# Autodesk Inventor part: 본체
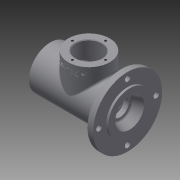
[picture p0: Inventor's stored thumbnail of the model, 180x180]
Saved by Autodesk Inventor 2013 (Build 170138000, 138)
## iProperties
Created: 2016-08
Part Number: 본체
Material: 일반
Document SubType Name: Modeling
Designer: Administrator
Density: 1 g/cm^3
Author: Administrator
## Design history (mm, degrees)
sketch "스케치1"
  geometry: C1 r 31 at (0, 0); C2 r 26 at (0, 0); 1 further point
  constraints: 2 centre point, 2 coincident
  dimensions: "d8" = 62 diameter of C1; "d9" = 52 diameter of C2
extrude "돌출1" new body sketch "스케치1" stored distance "d10" = 115; taper "d11" = 0 deg
sketch "스케치2"
  geometry: L1 (-57.5, -31)-(-57.5, 31) reference; L2 (-57.5, 31)-(57.5, 31) reference; L3 (57.5, 31)-(57.5, -31) reference; L4 (57.5, -31)-(-57.5, -31) reference; L5 (0, 0)-(57.5, 0); L6 (44.5, 31)-(54.5, 31); L7 (54.5, 31)-(54.5, 50); L8 (54.5, 50)-(44.5, 50); L9 (44.5, 50)-(44.5, 31)
  constraints: 10 end point, 2 parallel, 1 horizontal, 1 midpoint, 1 perpendicular, 1 point on line
  dimensions: "d12" = 3 distance between parallel lines of L3 L7; "d13" = 13 distance between parallel lines of L3 L9; "d14" = 100 diameter of L8 L5
revolve "회전1" sketch "스케치2" stored, may be unused: angle "d15" = 90 deg
node "작업 평면1"
sketch "스케치4"
  geometry: L1 (44.5, 31)-(44.5, -31) reference; L2 (-57.5, 31)-(-57.5, -31) reference; L3 (-57.5, 0)-(0, 0); C1 r 30 at (-1.5, 0)
  constraints: 2 end point, 1 centre point, 1 midpoint, 1 perpendicular, 1 point on line
  dimensions: "d47" = 60 diameter of C1; "d48" = 56 distance from line of L2 C1.centre
extrude "돌출3" join sketch "스케치4" stored distance "d49" = 0; taper "d50" = 0 deg
sketch "스케치5" dims "d60" = 48
  geometry: L1 (0, 0)-(0, 24); C1 r 30 at (0, 0) reference; 2 further points
  constraints: 2 coincident, 2 end point, 1 vertical, 1 vertical alignment, 2 other
hole "구멍2" sketch "스케치5" at (0, 24) diameter "d61" = 3.459; stored, may be unused: countersink angle "d65" = 90 deg, drill point angle "d67" = 118 deg; dims "d62" = 8, "d63" = 4, "d64" = 2, "d66" = 10
sketch "스케치7" dims "d80" = 83
  geometry: L1 (0, 0)-(0, 41.5); 2 further points
  constraints: 2 coincident, 2 end point, 1 vertical, 1 vertical alignment, 2 other
hole "구멍3" sketch "스케치7" at (0, 41.5) diameter "d81" = 8; stored, may be unused: countersink angle "d85" = 90 deg, drill point angle "d87" = 118 deg; dims "d82" = 8, "d83" = 4, "d84" = 2, "d86" = 10
node "작업 평면2"
sketch "스케치8" dims "d95" = 3
  geometry: L1 (-21.122, -6.998)-(21.122, -6.998); L2 (21.122, -6.998)-(21.122, -13.002); L3 (21.122, -13.002)-(-21.122, -13.002); L4 (-21.122, -13.002)-(-21.122, -6.998); L5 (-21.122, -10)-(21.122, -10); L6 (0, -13.002)-(0, -6.998); L7 (-30, 0)-(30, 0) reference; L8 (-56, -18)-(-56, -80) reference; 1 further point
  constraints: 4 end point, 4 midpoint, 2 other
  dimensions: "d91" = 10 distance between parallel lines of L5 L7; "d92" = 56 distance between parallel lines of L8 L6
feature "엠보싱1" sketch "스케치8" dims "d11" = 0, "d93" = 0.5, "d94" = 0
fillet "모깎기1" dims "d95" = 3
sketch "스케치10"
  geometry: L1 (-44.5, 47)-(-44.5, 45.5) reference; L2 (-44.5, 45.5)-(-54.5, 45.5) reference; L3 (-54.5, 45.5)-(-54.5, 50) reference; L4 (-54.5, 50)-(-47.5, 50) reference; L5 (-47.5, -50)-(-54.5, -50) reference; L6 (-54.5, -50)-(-54.5, -45.5) reference; L7 (-54.5, -45.5)-(-44.5, -45.5) reference; L8 (-44.5, -45.5)-(-44.5, -47) reference; L9 (-24.23, 39)-(-22.5, 37.961) reference; L10 (-22.5, 37.961)-(-20.771, 39) reference; L11 (-20.771, 39)-(-20.771, 49) reference; L12 (-20.771, 49)-(23.77, 49) reference; L13 (23.77, 49)-(23.77, 39) reference; L14 (23.77, 39)-(25.5, 37.961) reference; L15 (25.5, 37.961)-(27.23, 39) reference; L16 (27.23, 39)-(27.23, 49) reference; L17 (27.23, 49)-(31.5, 49) reference; L18 (31.5, 49)-(31.5, 34) reference; L19 (34.5, 31)-(57.5, 31) reference; L20 (57.5, 31)-(57.5, -31) reference; L21 (57.5, -31)-(-41.5, -31) reference; L22 (-44.5, -34)-(-44.5, -37.5) reference; L23 (-44.5, -37.5)-(-54.5, -37.5) reference; L24 (-54.5, -37.5)-(-54.5, -31) reference; L25 (-54.5, -31)-(-57.5, -31) reference; L26 (-57.5, -31)-(-57.5, 31) reference; L27 (-57.5, 31)-(-54.5, 31) reference; L28 (-54.5, 31)-(-54.5, 37.5) reference; L29 (-54.5, 37.5)-(-44.5, 37.5) reference; L30 (-44.5, 37.5)-(-44.5, 34) reference; L31 (-41.5, 31)-(-31.5, 31) reference; L32 (-28.5, 34)-(-28.5, 49) reference; L33 (-28.5, 49)-(-24.23, 49) reference; L34 (-24.23, 49)-(-24.23, 39) reference; L35 (-44.5, 47)-(-44.5, 45.5) reference; L36 (-44.5, 45.5)-(-54.5, 45.5) reference; L37 (-54.5, 45.5)-(-54.5, 50) reference; L38 (-54.5, 50)-(-47.5, 50) reference; L39 (-47.5, -50)-(-54.5, -50) reference; L40 (-54.5, -50)-(-54.5, -45.5) reference; L41 (-54.5, -45.5)-(-44.5, -45.5) reference; L42 (-44.5, -45.5)-(-44.5, -47) reference; L43 (-24.23, 39)-(-22.5, 37.961) reference; L44 (-22.5, 37.961)-(-20.771, 39) reference; L45 (-20.771, 39)-(-20.771, 49) reference; L46 (-20.771, 49)-(23.77, 49) reference; L47 (23.77, 49)-(23.77, 39) reference; L48 (23.77, 39)-(25.5, 37.961) reference; L49 (25.5, 37.961)-(27.23, 39) reference; L50 (27.23, 39)-(27.23, 49) reference; L51 (27.23, 49)-(31.5, 49) reference; L52 (31.5, 49)-(31.5, 34) reference; L53 (34.5, 31)-(57.5, 31) reference; L54 (57.5, 31)-(57.5, -31) reference; L55 (57.5, -31)-(-41.5, -31) reference; L56 (-44.5, -34)-(-44.5, -37.5) reference; L57 (-44.5, -37.5)-(-54.5, -37.5) reference; L58 (-54.5, -37.5)-(-54.5, -31) reference; L59 (-54.5, -31)-(-57.5, -31) reference; L60 (-57.5, -31)-(-57.5, 31) reference; L61 (-57.5, 31)-(-54.5, 31) reference; L62 (-54.5, 31)-(-54.5, 37.5) reference; L63 (-54.5, 37.5)-(-44.5, 37.5) reference; L64 (-44.5, 37.5)-(-44.5, 34) reference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; A1 r 3 centre (-47.5, 47) between (-44.5, 47) and (-47.5, 50) reference; A2 r 3 centre (-47.5, -47) between (-47.5, -50) and (-44.5, -47) reference; A3 r 3 centre (-41.5, -34) between (-41.5, -31) and (-44.5, -34) reference; A4 r 3 centre (-41.5, 34) between (-44.5, 34) and (-41.5, 31) reference; A5 r 3 centre (-47.5, 47) between (-44.5, 47) and (-47.5, 50) reference; A6 r 3 centre (-47.5, -47) between (-47.5, -50) and (-44.5, -47) reference; A7 r 3 centre (-41.5, -34) between (-41.5, -31) and (-44.5, -34) reference; A8 r 3 centre (-41.5, 34) between (-44.5, 34) and (-41.5, 31) reference; A9 r 3 centre (17.5, 23) between (20.5, 23) and (17.5, 26); A10 r 3 centre (-14.5, 23) between (-14.5, 26) and (-17.5, 23); A11 r 3 centre (-30.5, 13.5) between (-30.5, 16.5) and (-33.5, 13.5); A12 r 0.3 centre (36.8, 19.7) between (36.8, 20) and (36.5, 19.7); A13 r 0.3 centre (-36.5, 12.2) between (-36.2, 12.2) and (-36.5, 12.5); A14 r 3 centre (-46.5, 13.886) between (-43.5, 13.886) and (-45.491, 16.711); 6 further points
  constraints: 112 end point, 27 point on line, 26 parallel, 12 perpendicular, 12 point on circle, 12 tangent, 11 horizontal, 6 centre point, 4 equal radius, 3 collinear, 3 midpoint, 5 other
  dimensions: "d105" = 56 distance between parallel lines of L20 L69; "d106" = 12 distance between parallel lines of L20 L76; "d107" = 42 diameter of L73 L70; "d108" = 3 distance of L76.end L77.end; "d109" = 48 diameter of L77 L70; "d110" = 40 diameter of L81 L70; "d111" = 35 diameter of L85 L70; "d112" = 37 diameter of L89 L70; "d113" = 1.75 distance of L88.end L89.end; "d114" = 21 distance between parallel lines of L20 L86; "d116" = 38 distance between parallel lines of L92 L100; "d117" = 26 distance between parallel lines of L20 L84; "d118" = 35 diameter of L97 L70; "d119" = 5 distance of L101.start point (-33.5, 16.5); "d120" = 14 distance between parallel lines of L26 L110; "d121" = 32 diameter of point (-43.5, 16) L70; "d122" = 42 diameter of L95.start L70; "d123" = 86 distance between parallel lines of L20 L98; "d124" = 20 diameter of L107 L70; "d125" = 2.7 distance of L106.end L107.end; "d126" = 25 diameter of L111 L70; "d127" = 33 diameter of L101 L70; "d128" = 52 diameter of L115 L113; "d129" = 38 distance of point (-17.5, 26) point (20.5, 26); "d130" = 3 radius of A9; "d131" = 0.3 radius of A12; "d132" = 1 distance of L97.start L118.start; "d133" = 1 distance of L114.start L118.start (= d132); "d134" = 1 distance of L111.start L122.start; "d135" = 1 distance of L96.end L122.start (= d134); "d136" = 1 distance of L93.start L121.start; "d137" = 1 distance of L116.end L121.start (= d136)
  node "절단 모서리 투영4"
  node "절단 모서리 투영5"
revolve "회전4" stored, may be unused: angle "d138" = 90 deg
revolve "회전5" stored, may be unused: angle "d139" = 90 deg
revolve "회전6" stored, may be unused: angle "d140" = 90 deg
sketch "스케치11"
  geometry: L1 (-44.5, 47)-(-44.5, 45.5) reference; L2 (-44.5, 45.5)-(-54.5, 45.5) reference; L3 (-54.5, 45.5)-(-54.5, 50) reference; L4 (-54.5, 50)-(-47.5, 50) reference; L5 (-47.5, -50)-(-54.5, -50) reference; L6 (-54.5, -50)-(-54.5, -45.5) reference; L7 (-54.5, -45.5)-(-44.5, -45.5) reference; L8 (-44.5, -45.5)-(-44.5, -47) reference; L9 (-24.23, 39)-(-22.5, 37.961) reference; L10 (-22.5, 37.961)-(-20.771, 39) reference; L11 (-20.771, 39)-(-20.771, 49) reference; L12 (-20.771, 49)-(23.77, 49) reference; L13 (23.77, 49)-(23.77, 39) reference; L14 (23.77, 39)-(25.5, 37.961) reference; L15 (25.5, 37.961)-(27.23, 39) reference; L16 (27.23, 39)-(27.23, 49) reference; L17 (27.23, 49)-(31.5, 49) reference; L18 (31.5, 49)-(31.5, 34) reference; L19 (34.5, 31)-(57.5, 31) reference; L20 (57.5, 31)-(57.5, 21) reference; L21 (57.5, 21)-(48.5, 21) reference; L22 (48.5, 21)-(48.5, 24) reference; L23 (48.5, 24)-(45.5, 24) reference; L24 (45.5, 24)-(45.5, 20) reference; L25 (45.5, 20)-(36.8, 20) reference; L26 (36.5, 19.7)-(36.5, 17.5) reference; L27 (36.5, 17.5)-(31.5, 17.5) reference; L28 (31.5, 17.5)-(31.5, 18.5) reference; L29 (31.5, 18.5)-(29.75, 18.5) reference; L30 (29.75, 18.5)-(29.75, 17.5) reference; L31 (29.75, 17.5)-(21.5, 17.5) reference; L32 (21.5, 17.5)-(20.5, 18.5) reference; L33 (20.5, 18.5)-(20.5, 23) reference; L34 (17.5, 26)-(-14.5, 26) reference; L35 (-17.5, 23)-(-17.5, 18.5) reference; L36 (-17.5, 18.5)-(-18.5, 17.5) reference; L37 (-18.5, 17.5)-(-28.5, 17.5) reference; L38 (-28.5, 17.5)-(-28.5, -17.5) reference; L39 (-28.5, -17.5)-(-18.5, -17.5) reference; L40 (-18.5, -17.5)-(-17.5, -18.5) reference; L41 (-17.5, -18.5)-(-17.5, -23) reference; L42 (-14.5, -26)-(17.5, -26) reference; L43 (20.5, -23)-(20.5, -18.5) reference; L44 (20.5, -18.5)-(21.5, -17.5) reference; L45 (21.5, -17.5)-(29.75, -17.5) reference; L46 (29.75, -17.5)-(29.75, -18.5) reference; L47 (29.75, -18.5)-(31.5, -18.5) reference; L48 (31.5, -18.5)-(31.5, -17.5) reference; L49 (31.5, -17.5)-(36.5, -17.5) reference; L50 (36.5, -17.5)-(36.5, -19.7) reference; L51 (36.8, -20)-(45.5, -20) reference; L52 (45.5, -20)-(45.5, -24) reference; L53 (45.5, -24)-(48.5, -24) reference; L54 (48.5, -24)-(48.5, -21) reference; L55 (48.5, -21)-(57.5, -21) reference; L56 (57.5, -21)-(57.5, -31) reference; L57 (57.5, -31)-(-41.5, -31) reference; L58 (-44.5, -34)-(-44.5, -37.5) reference; L59 (-44.5, -37.5)-(-54.5, -37.5) reference; L60 (-54.5, -37.5)-(-54.5, -31) reference; L61 (-54.5, -31)-(-57.5, -31) reference; L62 (-57.5, -31)-(-57.5, 31) reference; L63 (-57.5, 31)-(-54.5, 31) reference; L64 (-54.5, 31)-(-54.5, 37.5) reference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; A1 r 3 centre (-47.5, 47) between (-44.5, 47) and (-47.5, 50) reference; A2 r 3 centre (-47.5, -47) between (-47.5, -50) and (-44.5, -47) reference; A3 r 0.3 centre (36.8, 19.7) between (36.8, 20) and (36.5, 19.7) reference; A4 r 3 centre (17.5, 23) between (20.5, 23) and (17.5, 26) reference; A5 r 3 centre (-14.5, 23) between (-14.5, 26) and (-17.5, 23) reference; A6 r 3 centre (-14.5, -23) between (-17.5, -23) and (-14.5, -26) reference; A7 r 3 centre (17.5, -23) between (17.5, -26) and (20.5, -23) reference; A8 r 0.3 centre (36.8, -19.7) between (36.5, -19.7) and (36.8, -20) reference; A9 r 3 centre (-41.5, -34) between (-41.5, -31) and (-44.5, -34) reference; A10 r 3 centre (-41.5, 34) between (-44.5, 34) and (-41.5, 31) reference; A11 r 3 centre (-30.5, 13.5) between (-30.5, 16.5) and (-33.5, 13.5); A12 r 0.3 centre (-36.5, 12.2) between (-36.2, 12.2) and (-36.5, 12.5); 1 further point
  constraints: 30 end point, 6 parallel, 4 perpendicular, 4 point on circle, 4 point on line, 4 tangent, 3 horizontal, 2 centre point, 1 collinear, 1 midpoint, 2 other
  dimensions: "d141" = 32 diameter of L72.end L71; "d143" = 42 diameter of L72.start L71; "d144" = 14 distance between parallel lines of L62 L73; "d145" = 33 diameter of L82 L71; "d146" = 2.7 distance of L79.end L80.end; "d147" = 25 diameter of L76 L71; "d148" = 7.3 distance of point (-36.2, 12.5) L76.end; "d149" = 20 diameter of L80 L71; "d150" = 3 radius of A11; "d151" = 0.3 radius of A12
revolve "회전7" sketch "스케치11" stored, may be unused: angle "d152" = 90 deg
hole "구멍4" diameter "d155" = 38; stored, may be unused: countersink angle "d159" = 90 deg, drill point angle "d161" = 118 deg; dims "d153" = 10, "d154" = 10, "d156" = 8, "d157" = 4, "d158" = 2, "d160" = 10
feature "스레드2" dims "d162" = 10, "d163" = 0
chamfer "모따기2" distance "d164" = 1; stored, may be unused: second distance "d165" = 2, angle "d166" = 45 deg
fillet "모깎기3" dims "d167" = 3
node "솔리드1"
pattern_circular "원형 패턴1" dims angle "d69" = 360 deg
pattern_circular "원형 패턴2" dims angle "d89" = 360 deg
node "투영된 루프1"
node "투영된 루프2"
node "절단 모서리 투영1"
node "절단 모서리 투영6"
other parameters: "d46" = 49
